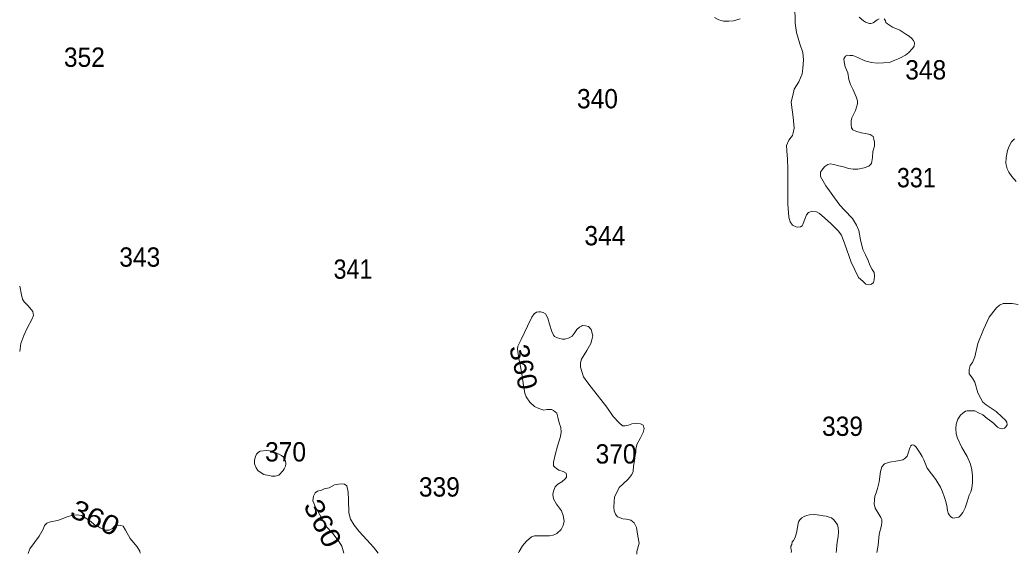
# Model space of a CAD drawing. Extents: x 445.4 to 500, y 8728.7 to 8784.
# Drawn here: x 464.5 to 472.73, y 8728.69 to 8733.12 of the extents above; entities that cross this region are included whole.
import ezdxf
from ezdxf.enums import TextEntityAlignment as Align

# ---------------------------------------------------------------- set-up
doc = ezdxf.new("R2010")
doc.units = 0
doc.header["$LTSCALE"] = 0.064
doc.layers.add('2', color=7, linetype='Continuous', lineweight=13)
doc.layers.add('21', color=7, linetype='Continuous')
doc.layers.add('61', color=7, linetype='Continuous')

msp = doc.modelspace()

# ---------------------------------------------------------------- linework, layer by layer
at = {"layer": '2'}
for points in [[(471.5068, 8731.1746), (471.5292, 8731.1274), (471.5441, 8731.0878), (471.564, 8731.053), (471.5789, 8731.0258), (471.5814, 8730.9985), (471.5789, 8730.9655), (471.5739, 8730.9431), (471.5565, 8730.9307), (471.5366, 8730.9258), (471.5118, 8730.9307), (471.4845, 8730.9555), (471.4497, 8730.9853), (471.3901, 8731.1118), (471.3354, 8731.263), (471.3081, 8731.3374), (471.2807, 8731.3721), (471.2236, 8731.4292), (471.1689, 8731.4805), (471.1266, 8731.5152), (471.1018, 8731.5301), (471.067, 8731.5351), (471.0347, 8731.5227), (471.0198, 8731.5053), (470.9999, 8731.4557), (470.9875, 8731.4259), (470.9825, 8731.4135), (470.9701, 8731.4061), (470.9478, 8731.4036), (470.9328, 8731.4061), (470.903, 8731.4185), (470.8832, 8731.4458), (470.8732, 8731.4855), (470.8658, 8731.5921), (470.8633, 8731.8822), (470.8608, 8731.9665), (470.8553, 8732.0352), (470.8529, 8732.0799), (470.8727, 8732.122), (470.8926, 8732.1468), (470.9026, 8732.1617), (470.91, 8732.184), (470.9175, 8732.2237), (470.9075, 8732.313), (470.8976, 8732.3948), (470.8926, 8732.4419), (470.905, 8732.494), (470.9175, 8732.5461), (470.9551, 8732.6049), (470.9825, 8732.6719), (470.9899, 8732.7165), (470.9949, 8732.7884), (470.9899, 8732.8504), (470.9626, 8732.9223), (470.9353, 8733.0141), (470.9253, 8733.091), (470.9229, 8733.2363)], [(470.4694, 8733.1294), (470.4147, 8733.112), (470.375, 8733.1096), (470.3328, 8733.1096), (470.293, 8733.1195), (470.2582, 8733.1393)], [(471.6614, 8733.1277), (471.6725, 8733.1125), (471.6767, 8733.0972), (471.6892, 8733.0875), (471.7073, 8733.0764), (471.7323, 8733.0584), (471.7934, 8733.0348), (471.8406, 8733.0016), (471.8684, 8732.9835), (471.8906, 8732.9655), (471.9045, 8732.9475), (471.9128, 8732.9295), (471.9115, 8732.9017), (471.8962, 8732.8837), (471.867, 8732.8504), (471.8396, 8732.8259), (471.7924, 8732.8036), (471.7502, 8732.7863), (471.7055, 8732.7664), (471.6558, 8732.7639), (471.604, 8732.7612), (471.5568, 8732.7661), (471.5022, 8732.781), (471.445, 8732.8083), (471.4028, 8732.8231), (471.3779, 8732.8256), (471.3581, 8732.8281), (471.3432, 8732.8182), (471.3283, 8732.7959), (471.3307, 8732.7711), (471.3407, 8732.7314), (471.3606, 8732.6818), (471.3705, 8732.6248), (471.3829, 8732.5851), (471.4053, 8732.5405), (471.4301, 8732.4834), (471.4401, 8732.4487), (471.4425, 8732.4239), (471.4252, 8732.3693), (471.3953, 8732.3085), (471.3903, 8732.2837), (471.3878, 8732.2515), (471.3928, 8732.2242), (471.4027, 8732.2093), (471.4276, 8732.1969), (471.4723, 8732.1845), (471.5071, 8732.1796), (471.5468, 8732.1697), (471.5717, 8732.1523), (471.5766, 8732.1325), (471.5816, 8732.1052), (471.5816, 8732.0729), (471.5692, 8732.0283), (471.5667, 8731.9787), (471.5562, 8731.9303), (471.5364, 8731.908), (471.4966, 8731.8931), (471.4444, 8731.8832), (471.4047, 8731.8832), (471.3674, 8731.8881), (471.3252, 8731.903), (471.2879, 8731.9105), (471.2457, 8731.9229), (471.2159, 8731.9278), (471.196, 8731.9204), (471.1711, 8731.9055), (471.1537, 8731.8857), (471.1364, 8731.8584), (471.1364, 8731.8212), (471.1562, 8731.784), (471.1786, 8731.7443), (471.2084, 8731.7046), (471.2506, 8731.6451), (471.2954, 8731.5856), (471.3351, 8731.5435), (471.4, 8731.473), (471.4323, 8731.4185), (471.4522, 8731.3738), (471.4671, 8731.297), (471.487, 8731.2167), (471.5068, 8731.1746)], [(471.4549, 8733.1408), (471.4914, 8733.1123), (471.5088, 8733.0996), (471.5396, 8733.0881), (471.5524, 8733.0893), (471.5716, 8733.0941), (471.6031, 8733.1194), (471.6197, 8733.1291)], [(472.7561, 8731.7796), (472.721, 8731.8214), (472.6942, 8731.8581), (472.6808, 8731.8865), (472.6707, 8731.93), (472.6724, 8731.9801), (472.6841, 8732.0386), (472.6975, 8732.0736), (472.7176, 8732.1087), (472.7427, 8732.1338)], [(464.5024, 8730.9127), (464.5183, 8730.843), (464.5246, 8730.805), (464.5405, 8730.7829), (464.5722, 8730.7512), (464.6103, 8730.7037), (464.6166, 8730.6721), (464.6039, 8730.6372), (464.5659, 8730.5708), (464.5373, 8730.5043), (464.5119, 8730.4378), (464.5024, 8730.3729)], [(468.6338, 8728.7041), (468.6381, 8728.7147), (468.6656, 8728.7615), (468.6987, 8728.8027), (468.7427, 8728.8384), (468.7675, 8728.8466), (468.8198, 8728.8466), (468.8914, 8728.8466), (468.9217, 8728.8521), (468.952, 8728.8659), (468.9878, 8728.8989), (469.0043, 8728.9318), (469.0126, 8728.9676), (469.0043, 8729.0143), (468.9905, 8729.0528), (468.9492, 8729.1077), (468.9245, 8729.1517), (468.919, 8729.1874), (468.9245, 8729.2149), (468.9382, 8729.2506), (468.9603, 8729.2726), (468.9933, 8729.2918), (469.0214, 8729.3184), (469.0324, 8729.3321), (469.0324, 8729.3458), (469.0296, 8729.3651), (469.0049, 8729.3788), (468.9691, 8729.3898), (468.9498, 8729.4035), (468.936, 8729.4145), (468.925, 8729.4255), (468.925, 8729.4558), (468.9388, 8729.5162), (468.958, 8729.5877), (468.9828, 8729.6674), (468.9883, 8729.7031), (468.9856, 8729.7443), (468.9718, 8729.7828), (468.9608, 8729.8295), (468.9525, 8729.8625), (468.925, 8729.8845), (468.9057, 8729.8927), (468.8672, 8729.8927), (468.8424, 8729.8872), (468.8011, 8729.901), (468.7653, 8729.9174), (468.7268, 8729.9532), (468.6964, 8729.9961), (468.6854, 8730.0263), (468.6744, 8730.0923), (468.6606, 8730.1885), (468.6496, 8730.2489), (468.6358, 8730.3149), (468.6275, 8730.3726), (468.6248, 8730.3918), (468.6275, 8730.4165), (468.6551, 8730.4715), (468.7076, 8730.5827), (468.7434, 8730.6569), (468.7627, 8730.6844), (468.7819, 8730.6981), (468.8012, 8730.7008), (468.815, 8730.7008), (468.837, 8730.6953), (468.8563, 8730.6844), (468.8755, 8730.6486), (468.8893, 8730.5992), (468.9086, 8730.5387), (468.9223, 8730.5085), (468.9306, 8730.4975), (468.9554, 8730.4865), (468.9774, 8730.481), (468.9994, 8730.4755), (469.0187, 8730.4755), (469.0545, 8730.4865), (469.0793, 8730.5002), (469.0958, 8730.5222), (469.1178, 8730.5552), (469.1399, 8730.5744), (469.1564, 8730.5827), (469.1646, 8730.5882), (469.1894, 8730.5854), (469.2142, 8730.5799), (469.2362, 8730.5552), (469.25, 8730.503), (469.2417, 8730.47), (469.2335, 8730.4398), (469.2004, 8730.3821), (469.1784, 8730.3436), (469.1564, 8730.3079), (469.1481, 8730.2776), (469.1481, 8730.2419), (469.1591, 8730.2062), (469.1729, 8730.1622), (469.2087, 8730.1128), (469.2362, 8730.077), (469.3653, 8729.9117), (469.4189, 8729.8353), (469.4686, 8729.7808), (469.4954, 8729.7578), (469.5184, 8729.7578)], [(472.3677, 8730.2245), (472.3734, 8730.2562), (472.3937, 8730.2821), (472.4139, 8730.3283), (472.437, 8730.4378), (472.4861, 8730.556), (472.5325, 8730.656), (472.5701, 8730.7056), (472.5919, 8730.734), (472.6186, 8730.7556), (472.647, 8730.769), (472.6854, 8730.769), (472.7222, 8730.769), (472.7723, 8730.7623)], [(471.602, 8728.707), (471.6119, 8728.7676), (471.6214, 8728.8584), (471.6403, 8728.9315), (471.6437, 8728.958), (471.6437, 8728.9816), (471.6353, 8728.9984), (471.61, 8729.0389), (471.588, 8729.076), (471.5795, 8729.1114), (471.5812, 8729.1434), (471.5863, 8729.1738), (471.5948, 8729.2024), (471.6083, 8729.2378), (471.6218, 8729.2935), (471.6319, 8729.3778), (471.6421, 8729.4162), (471.6421, 8729.4162), (471.6657, 8729.4414), (471.7063, 8729.4566), (471.7755, 8729.4667), (471.8161, 8729.4752), (471.8347, 8729.487), (471.8515, 8729.5055), (471.8651, 8729.5392), (471.8711, 8729.5665), (471.8766, 8729.5805), (471.882, 8729.5914), (471.8875, 8729.5975), (471.8955, 8729.5987), (471.9077, 8729.5975), (471.9174, 8729.5921), (471.9272, 8729.5805), (471.9442, 8729.5561), (471.9607, 8729.5318), (471.9784, 8729.502), (471.9906, 8729.4752), (472.0188, 8729.406), (472.0543, 8729.3605), (472.0897, 8729.3133), (472.1073, 8729.2855), (472.1276, 8729.2484), (472.1445, 8729.2113), (472.1597, 8729.1725), (472.1715, 8729.1371), (472.18, 8729.0966), (472.1867, 8729.0562), (472.1919, 8729.0335), (472.2003, 8729.02), (472.2138, 8729.0032), (472.2274, 8728.9947), (472.2426, 8728.9931), (472.2628, 8728.9964), (472.2797, 8728.9998), (472.2949, 8729.015), (472.3135, 8729.0386), (472.3321, 8729.0774), (472.3507, 8729.1279), (472.3676, 8729.1819), (472.3794, 8729.2089), (472.3878, 8729.2392), (472.3946, 8729.2864), (472.3948, 8729.3434), (472.3897, 8729.3923), (472.3762, 8729.4395), (472.3508, 8729.5019), (472.3069, 8729.5778), (472.2685, 8729.6549), (472.2578, 8729.6915), (472.2548, 8729.7342), (472.2578, 8729.7693), (472.2731, 8729.812), (472.2945, 8729.8441), (472.3129, 8729.8624), (472.3358, 8729.8776), (472.3496, 8729.8807), (472.4138, 8729.8822), (472.4428, 8729.8654), (472.4795, 8729.8471), (472.5162, 8729.8181), (472.5544, 8729.7891), (472.5702, 8729.7771), (472.6012, 8729.7461), (472.6231, 8729.7351), (472.6451, 8729.7333), (472.6578, 8729.737), (472.6706, 8729.7479), (472.6816, 8729.7661), (472.6779, 8729.7862), (472.667, 8729.8044), (472.6359, 8729.8317), (472.5903, 8729.8755), (472.5483, 8729.9028), (472.5063, 8729.9301), (472.4803, 8729.9535), (472.463, 8729.9823), (472.437, 8730.0313), (472.4139, 8730.1178), (472.3937, 8730.1524), (472.3677, 8730.187), (472.3677, 8730.2245)], [(469.5184, 8729.7578), (469.5452, 8729.7617), (469.5719, 8729.7731), (469.6102, 8729.7769), (469.6447, 8729.7731), (469.6676, 8729.7617), (469.6753, 8729.7349), (469.6676, 8729.7005), (469.6408, 8729.6509), (469.6179, 8729.6089), (469.6064, 8729.5668), (469.6064, 8729.5401), (469.5987, 8729.5134), (469.5949, 8729.4675), (469.5872, 8729.4255), (469.5834, 8729.3797), (469.5719, 8729.3529), (469.5413, 8729.3147), (469.4992, 8729.2727), (469.4686, 8729.246), (469.4452, 8729.1983), (469.4299, 8729.1678), (469.4261, 8729.1296), (469.4222, 8729.0799), (469.4261, 8729.0532), (469.4376, 8729.0264), (469.4529, 8729.0035), (469.4967, 8728.9857), (469.5288, 8728.983), (469.5639, 8728.9768), (469.5906, 8728.9539), (469.6098, 8728.9157), (469.6213, 8728.8431), (469.6327, 8728.7858), (469.6136, 8728.717), (469.6136, 8728.6941)], [(467.1884, 8728.7026), (467.1695, 8728.7589), (467.1498, 8728.795), (467.0972, 8728.8639), (467.0347, 8728.9295), (466.9985, 8729.0017), (466.9525, 8729.0838), (466.9295, 8729.1363), (466.9361, 8729.1756), (466.9492, 8729.2019), (466.9689, 8729.215), (467.0018, 8729.2249), (467.0248, 8729.2347), (467.0643, 8729.2445), (467.1103, 8729.2675), (467.1432, 8729.2741), (467.1728, 8729.2774), (467.1925, 8729.2741), (467.2122, 8729.261), (467.2221, 8729.2085), (467.2254, 8729.1428), (467.2289, 8729.036), (467.2414, 8728.9839), (467.2714, 8728.9328), (467.3142, 8728.8803), (467.3766, 8728.8114), (467.4325, 8728.7523), (467.472, 8728.7029)], [(464.5725, 8728.6998), (464.5876, 8728.7389), (464.6261, 8728.7911), (464.6647, 8728.8433), (464.6977, 8728.9011), (464.7088, 8728.9313), (464.728, 8728.9506), (464.7584, 8728.9616), (464.8162, 8728.9726), (464.8548, 8728.9863), (464.8878, 8729), (464.9402, 8729.0165), (464.9787, 8729.0193), (465.0145, 8729.0138), (465.0586, 8728.9863), (465.0917, 8728.9643), (465.1192, 8728.9396), (465.144, 8728.9286), (465.1688, 8728.9121), (465.1963, 8728.8983), (465.2129, 8728.8928), (465.2432, 8728.8928), (465.2707, 8728.9066), (465.29, 8728.9286), (465.3176, 8728.9341), (465.3396, 8728.9313), (465.3589, 8728.9258), (465.3782, 8728.8928), (465.4167, 8728.8241), (465.4746, 8728.7553), (465.4966, 8728.7196), (465.5001, 8728.7008)], [(470.8919, 8728.7063), (470.8937, 8728.7215), (470.8893, 8728.7439), (470.8893, 8728.7589), (470.8982, 8728.7753), (470.9012, 8728.7947), (470.9117, 8728.8081), (470.9237, 8728.8276), (470.9312, 8728.8515), (470.9386, 8728.8828), (470.9461, 8728.9336), (470.9536, 8728.962), (470.9641, 8728.9784), (470.9805, 8728.9948), (470.9985, 8729.0068), (471.0179, 8729.0142), (471.0449, 8729.0187), (471.0883, 8729.0217), (471.1257, 8729.0172), (471.1571, 8729.0127), (471.1825, 8729.0083), (471.2065, 8729.0008), (471.2259, 8728.9948), (471.2469, 8728.9754), (471.2618, 8728.956), (471.2768, 8728.9381), (471.2813, 8728.9127), (471.2843, 8728.8783), (471.2813, 8728.841), (471.2768, 8728.8096), (471.2708, 8728.7723), (471.2663, 8728.7305), (471.2635, 8728.7067)]]:
    msp.add_lwpolyline(points, dxfattribs=at)
msp.add_lwpolyline([(466.5099, 8729.3632), (466.4751, 8729.3864), (466.4606, 8729.4095), (466.4476, 8729.4414), (466.4476, 8729.4732), (466.4548, 8729.5036), (466.465, 8729.5224), (466.4795, 8729.5383), (466.4954, 8729.547), (466.5476, 8729.5514), (466.5708, 8729.5499), (466.6085, 8729.5427), (466.6477, 8729.5224), (466.6709, 8729.5108), (466.6869, 8729.4978), (466.697, 8729.4848), (466.7043, 8729.4674), (466.7057, 8729.4428), (466.7028, 8729.4225), (466.6941, 8729.4008), (466.6854, 8729.3878), (466.6723, 8729.3748), (466.6593, 8729.3589), (466.6477, 8729.3487), (466.6187, 8729.34), (466.5868, 8729.34), (466.5737, 8729.3444), (466.536, 8729.3502), (466.5244, 8729.3531)], close=True, dxfattribs=at)

# ---------------------------------------------------------------- texts
at = {"layer": '21'}
for s, width, p in [('352', 0.95, (464.8688, 8732.7304)), ('348', 0.95, (471.8371, 8732.6256)), ('340', 0.95, (469.1181, 8732.3867)), ('331', 0.9, (471.7678, 8731.7326)), ('344', 0.95, (469.1795, 8731.252)), ('343', 0.95, (465.3273, 8731.0749)), ('341', 0.9, (467.1022, 8730.975)), ('339', 0.95, (471.1479, 8729.6734)), ('370', 0.95, (466.535, 8729.4617)), ('370', 0.95, (469.2724, 8729.4444)), ('339', 0.95, (467.8088, 8729.1707))]:
    msp.add_text(s, height=0.16, dxfattribs=dict(at, width=width)).set_placement(p)
at = {"layer": '61'}
for rotation, width, p in [(283.231, 1.05, (468.5979, 8730.226)), (297.086, 1.15, (466.9419, 8728.9134)), (335.55, 1.15, (465.0949, 8728.923))]:
    msp.add_text('360', height=0.16, rotation=rotation, dxfattribs=dict(at, width=width)).set_placement(p, align=Align.CENTER)

doc.saveas('drawing.dxf')
